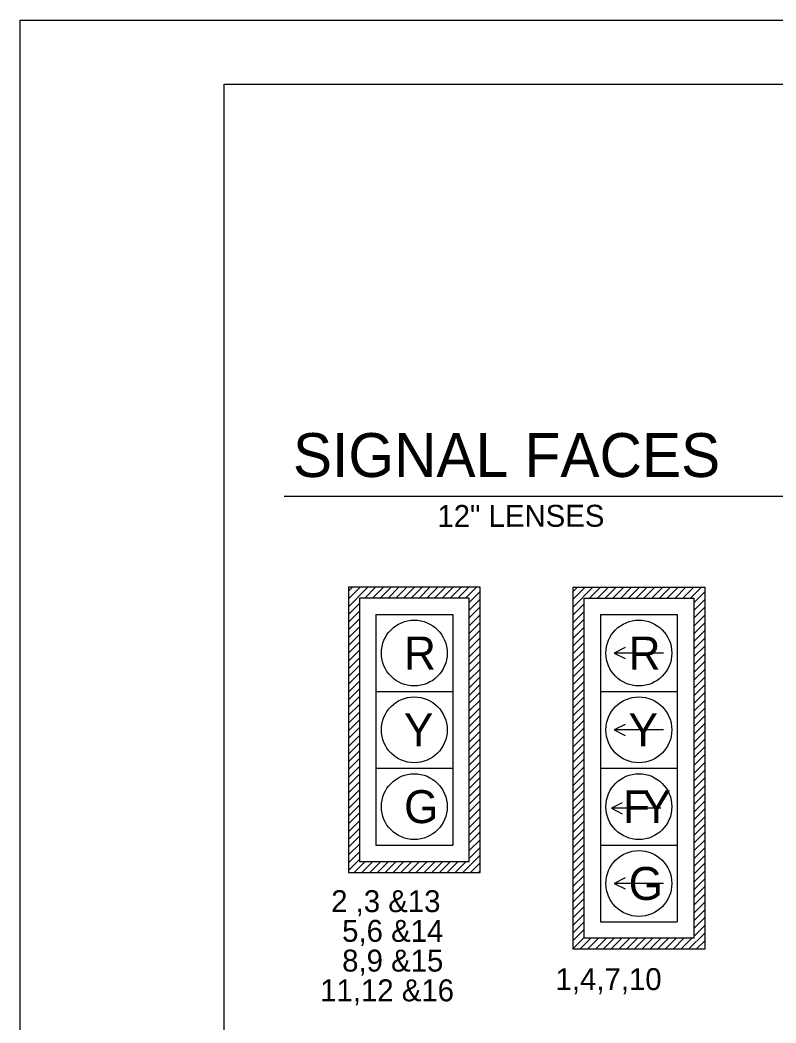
# Model space of a CAD drawing. Extents: x 641001 to 642001, y 326365 to 327005.
# Drawn here: x 641001.3 to 641139.1, y 326822.2 to 327005 of the extents above; entities that cross this region are included whole.
import ezdxf

# ---------------------------------------------------------------- set-up
doc = ezdxf.new("R2010")
doc.units = 0
for name, color, linetype in [('R_Border', 7, 'Continuous'), ('R_No Plot', 7, 'Continuous'), ('T_Drafting', 7, 'Continuous'), ('T_Notes', 7, 'Continuous')]:
    doc.layers.add(name, color=color, linetype=linetype)

msp = doc.modelspace()

# ---------------------------------------------------------------- linework, layer by layer
at = {"layer": 'R_Border'}
for p, q in [((641038.57, 326993.34), (641987.11, 326993.34)), ((641038.57, 326376.96), (641038.57, 326993.34))]:
    msp.add_line(p, q, dxfattribs=at)
at = {"layer": 'R_No Plot'}
msp.add_line((641001.36, 327005.02), (642001.36, 327005.02), dxfattribs=at)
msp.add_lwpolyline([(641001.34, 327005.02), (642001.36, 327005.02), (642001.36, 326365.01), (641001.34, 326365.01)], close=True, dxfattribs=at)
at = {"layer": 'T_Drafting'}
for p, q in [((641085.2, 326901.64), (641061.2, 326901.64)), ((641061.2, 326901.64), (641061.2, 326849.64)), ((641061.2, 326898.09), (641064.75, 326901.64)), ((641061.2, 326899.5), (641063.34, 326901.64)), ((641061.2, 326900.92), (641061.92, 326901.64)), ((641064.16, 326899.64), (641066.16, 326901.64)), ((641065.58, 326899.64), (641067.58, 326901.64)), ((641066.99, 326899.64), (641068.99, 326901.64)), ((641068.41, 326899.64), (641070.41, 326901.64)), ((641069.82, 326899.64), (641071.82, 326901.64)), ((641071.24, 326899.64), (641073.24, 326901.64)), ((641072.65, 326899.64), (641074.65, 326901.64)), ((641074.06, 326899.64), (641076.06, 326901.64)), ((641075.48, 326899.64), (641077.48, 326901.64)), ((641076.89, 326899.64), (641078.89, 326901.64)), ((641078.31, 326899.64), (641080.31, 326901.64)), ((641079.72, 326899.64), (641081.72, 326901.64)), ((641081.14, 326899.64), (641083.14, 326901.64)), ((641082.55, 326899.64), (641084.55, 326901.64)), ((641083.2, 326898.88), (641085.2, 326900.88)), ((641085.2, 326849.64), (641085.2, 326901.64)), ((641102.14, 326835.64), (641102.14, 326901.64)), ((641102.14, 326901.64), (641126.14, 326901.64)), ((641102.14, 326898.03), (641105.75, 326901.64)), ((641102.14, 326899.44), (641104.33, 326901.64)), ((641102.14, 326900.86), (641102.92, 326901.64)), ((641105.16, 326899.64), (641107.16, 326901.64)), ((641106.58, 326899.64), (641108.58, 326901.64)), ((641107.99, 326899.64), (641109.99, 326901.64)), ((641109.41, 326899.64), (641111.41, 326901.64)), ((641110.82, 326899.64), (641112.82, 326901.64)), ((641112.23, 326899.64), (641114.23, 326901.64)), ((641113.65, 326899.64), (641115.65, 326901.64)), ((641115.06, 326899.64), (641117.06, 326901.64)), ((641116.48, 326899.64), (641118.48, 326901.64)), ((641117.89, 326899.64), (641119.89, 326901.64)), ((641119.3, 326899.64), (641121.3, 326901.64)), ((641120.72, 326899.64), (641122.72, 326901.64)), ((641122.13, 326899.64), (641124.13, 326901.64)), ((641123.55, 326899.64), (641125.55, 326901.64)), ((641124.14, 326898.82), (641126.14, 326900.82)), ((641126.14, 326901.64), (641126.14, 326835.64)), ((641061.2, 326896.67), (641063.2, 326898.67)), ((641083.2, 326897.46), (641085.2, 326899.46)), ((641102.14, 326896.61), (641104.14, 326898.61)), ((641124.14, 326897.4), (641126.14, 326899.4)), ((641061.2, 326895.26), (641063.2, 326897.26)), ((641066.2, 326896.64), (641080.2, 326896.64)), ((641066.2, 326896.64), (641066.2, 326882.64)), ((641080.2, 326896.64), (641080.2, 326882.64)), ((641083.2, 326896.05), (641085.2, 326898.05)), ((641083.2, 326894.63), (641085.2, 326896.63)), ((641102.14, 326895.2), (641104.14, 326897.2)), ((641107.14, 326896.64), (641121.14, 326896.64)), ((641107.14, 326896.64), (641107.14, 326882.64)), ((641121.14, 326896.64), (641121.14, 326882.64)), ((641124.14, 326895.99), (641126.14, 326897.99)), ((641124.14, 326894.57), (641126.14, 326896.57)), ((641061.2, 326893.85), (641063.2, 326895.85)), ((641083.2, 326893.22), (641085.2, 326895.22)), ((641102.14, 326893.79), (641104.14, 326895.79)), ((641124.14, 326893.16), (641126.14, 326895.16)), ((641061.2, 326892.43), (641063.2, 326894.43)), ((641061.2, 326891.02), (641063.2, 326893.02)), ((641083.2, 326891.8), (641085.2, 326893.8)), ((641102.14, 326892.37), (641104.14, 326894.37)), ((641102.14, 326890.96), (641104.14, 326892.96)), ((641124.14, 326891.74), (641126.14, 326893.74)), ((641061.2, 326889.6), (641063.2, 326891.6)), ((641083.2, 326890.39), (641085.2, 326892.39)), ((641083.2, 326888.98), (641085.2, 326890.98)), ((641102.14, 326889.54), (641104.14, 326891.54)), ((641124.14, 326890.33), (641126.14, 326892.33)), ((641124.14, 326888.92), (641126.14, 326890.92)), ((641061.2, 326888.19), (641063.2, 326890.19)), ((641083.2, 326887.56), (641085.2, 326889.56)), ((641102.14, 326888.13), (641104.14, 326890.13)), ((641118.64, 326889.64), (641109.64, 326889.64)), ((641124.14, 326887.5), (641126.14, 326889.5)), ((641061.2, 326886.78), (641063.2, 326888.78)), ((641061.2, 326885.36), (641063.2, 326887.36)), ((641083.2, 326886.15), (641085.2, 326888.15)), ((641102.14, 326886.71), (641104.14, 326888.71)), ((641102.14, 326885.3), (641104.14, 326887.3)), ((641124.14, 326886.09), (641126.14, 326888.09)), ((641061.2, 326883.95), (641063.2, 326885.95)), ((641083.2, 326884.73), (641085.2, 326886.73)), ((641102.14, 326883.89), (641104.14, 326885.89)), ((641124.14, 326884.67), (641126.14, 326886.67)), ((641061.2, 326882.53), (641063.2, 326884.53)), ((641083.2, 326883.32), (641085.2, 326885.32)), ((641083.2, 326881.91), (641085.2, 326883.91)), ((641102.14, 326882.47), (641104.14, 326884.47)), ((641124.14, 326883.26), (641126.14, 326885.26)), ((641124.14, 326881.84), (641126.14, 326883.84)), ((641061.2, 326881.12), (641063.2, 326883.12)), ((641066.2, 326882.64), (641080.2, 326882.64)), ((641066.2, 326882.64), (641066.2, 326868.64)), ((641080.2, 326882.64), (641080.2, 326868.64)), ((641083.2, 326880.49), (641085.2, 326882.49)), ((641102.14, 326881.06), (641104.14, 326883.06)), ((641107.14, 326882.64), (641121.14, 326882.64)), ((641107.14, 326882.64), (641107.14, 326868.64)), ((641121.14, 326882.64), (641121.14, 326868.64)), ((641124.14, 326880.43), (641126.14, 326882.43)), ((641061.2, 326879.7), (641063.2, 326881.7)), ((641061.2, 326878.29), (641063.2, 326880.29)), ((641083.2, 326879.08), (641085.2, 326881.08)), ((641102.14, 326879.64), (641104.14, 326881.64)), ((641102.14, 326878.23), (641104.14, 326880.23)), ((641124.14, 326879.02), (641126.14, 326881.02)), ((641061.2, 326876.88), (641063.2, 326878.88)), ((641083.2, 326877.66), (641085.2, 326879.66)), ((641083.2, 326876.25), (641085.2, 326878.25)), ((641102.14, 326876.82), (641104.14, 326878.82)), ((641124.14, 326877.6), (641126.14, 326879.6)), ((641124.14, 326876.19), (641126.14, 326878.19)), ((641061.2, 326875.46), (641063.2, 326877.46)), ((641083.2, 326874.83), (641085.2, 326876.83)), ((641102.14, 326875.4), (641104.14, 326877.4)), ((641124.14, 326874.77), (641126.14, 326876.77)), ((641061.2, 326874.05), (641063.2, 326876.05)), ((641061.2, 326872.63), (641063.2, 326874.63)), ((641083.2, 326873.42), (641085.2, 326875.42)), ((641102.14, 326873.99), (641104.14, 326875.99)), ((641102.14, 326872.57), (641104.14, 326874.57)), ((641118.64, 326875.64), (641109.64, 326875.64)), ((641124.14, 326873.36), (641126.14, 326875.36)), ((641061.2, 326871.22), (641063.2, 326873.22)), ((641083.2, 326872.01), (641085.2, 326874.01)), ((641083.2, 326870.59), (641085.2, 326872.59)), ((641102.14, 326871.16), (641104.14, 326873.16)), ((641124.14, 326871.95), (641126.14, 326873.95)), ((641061.2, 326869.8), (641063.2, 326871.8)), ((641083.2, 326869.18), (641085.2, 326871.18)), ((641102.14, 326869.74), (641104.14, 326871.74)), ((641124.14, 326870.53), (641126.14, 326872.53)), ((641124.14, 326869.12), (641126.14, 326871.12)), ((641061.2, 326868.39), (641063.2, 326870.39)), ((641061.2, 326866.98), (641063.2, 326868.98)), ((641083.2, 326867.76), (641085.2, 326869.76)), ((641102.14, 326868.33), (641104.14, 326870.33)), ((641102.14, 326866.92), (641104.14, 326868.92)), ((641124.14, 326867.7), (641126.14, 326869.7)), ((641061.2, 326865.56), (641063.2, 326867.56)), ((641066.2, 326868.64), (641080.2, 326868.64)), ((641066.2, 326868.64), (641066.2, 326854.64)), ((641080.2, 326868.64), (641080.2, 326854.64)), ((641083.2, 326866.35), (641085.2, 326868.35)), ((641102.14, 326865.5), (641104.14, 326867.5)), ((641107.14, 326868.64), (641121.14, 326868.64)), ((641107.14, 326868.64), (641107.14, 326854.64)), ((641121.14, 326868.64), (641121.14, 326854.64)), ((641124.14, 326866.29), (641126.14, 326868.29)), ((641061.2, 326864.15), (641063.2, 326866.15)), ((641083.2, 326864.93), (641085.2, 326866.93)), ((641083.2, 326863.52), (641085.2, 326865.52)), ((641102.14, 326864.09), (641104.14, 326866.09)), ((641124.14, 326864.87), (641126.14, 326866.87)), ((641124.14, 326863.46), (641126.14, 326865.46)), ((641061.2, 326862.73), (641063.2, 326864.73)), ((641083.2, 326862.11), (641085.2, 326864.11)), ((641102.14, 326862.67), (641104.14, 326864.67)), ((641124.14, 326862.05), (641126.14, 326864.05)), ((641061.2, 326861.32), (641063.2, 326863.32)), ((641061.2, 326859.91), (641063.2, 326861.91)), ((641083.2, 326860.69), (641085.2, 326862.69)), ((641102.14, 326861.26), (641104.14, 326863.26)), ((641102.14, 326859.84), (641104.14, 326861.84)), ((641124.14, 326860.63), (641126.14, 326862.63)), ((641061.2, 326858.49), (641063.2, 326860.49)), ((641083.2, 326859.28), (641085.2, 326861.28)), ((641083.2, 326857.86), (641085.2, 326859.86)), ((641102.14, 326858.43), (641104.14, 326860.43)), ((641118.12, 326861.36), (641109.12, 326861.36)), ((641124.14, 326859.22), (641126.14, 326861.22)), ((641124.14, 326857.8), (641126.14, 326859.8)), ((641061.2, 326857.08), (641063.2, 326859.08)), ((641083.2, 326856.45), (641085.2, 326858.45)), ((641102.14, 326857.02), (641104.14, 326859.02)), ((641124.14, 326856.39), (641126.14, 326858.39)), ((641061.2, 326855.66), (641063.2, 326857.66)), ((641061.2, 326854.25), (641063.2, 326856.25)), ((641083.2, 326855.03), (641085.2, 326857.03)), ((641102.14, 326855.6), (641104.14, 326857.6)), ((641102.14, 326854.19), (641104.14, 326856.19)), ((641124.14, 326854.97), (641126.14, 326856.97)), ((641061.2, 326852.83), (641063.2, 326854.83)), ((641066.2, 326854.64), (641080.2, 326854.64)), ((641083.2, 326853.62), (641085.2, 326855.62)), ((641102.14, 326852.77), (641104.14, 326854.77)), ((641107.14, 326854.64), (641121.14, 326854.64)), ((641107.14, 326854.64), (641107.14, 326840.64)), ((641121.14, 326854.64), (641121.14, 326840.64)), ((641124.14, 326853.56), (641126.14, 326855.56)), ((641061.2, 326851.42), (641063.2, 326853.42)), ((641082.05, 326849.64), (641085.2, 326852.79)), ((641083.2, 326852.21), (641085.2, 326854.21)), ((641102.14, 326851.36), (641104.14, 326853.36)), ((641124.14, 326852.15), (641126.14, 326854.15)), ((641124.14, 326850.73), (641126.14, 326852.73)), ((641061.2, 326850.01), (641063.2, 326852.01)), ((641062.25, 326849.64), (641064.25, 326851.64)), ((641063.66, 326849.64), (641065.66, 326851.64)), ((641065.08, 326849.64), (641067.08, 326851.64)), ((641066.49, 326849.64), (641068.49, 326851.64)), ((641067.9, 326849.64), (641069.9, 326851.64)), ((641069.32, 326849.64), (641071.32, 326851.64)), ((641070.73, 326849.64), (641072.73, 326851.64)), ((641072.15, 326849.64), (641074.15, 326851.64)), ((641073.56, 326849.64), (641075.56, 326851.64)), ((641074.98, 326849.64), (641076.98, 326851.64)), ((641076.39, 326849.64), (641078.39, 326851.64)), ((641077.8, 326849.64), (641079.8, 326851.64)), ((641079.22, 326849.64), (641081.22, 326851.64)), ((641080.63, 326849.64), (641082.63, 326851.64)), ((641083.46, 326849.64), (641085.2, 326851.38)), ((641102.14, 326849.95), (641104.14, 326851.95)), ((641124.14, 326849.32), (641126.14, 326851.32)), ((641061.2, 326849.64), (641085.2, 326849.64)), ((641084.88, 326849.64), (641085.2, 326849.96)), ((641102.14, 326848.53), (641104.14, 326850.53)), ((641102.14, 326847.12), (641104.14, 326849.12)), ((641124.14, 326847.9), (641126.14, 326849.9)), ((641102.14, 326845.7), (641104.14, 326847.7)), ((641118.64, 326847.64), (641109.64, 326847.64)), ((641124.14, 326846.49), (641126.14, 326848.49)), ((641124.14, 326845.08), (641126.14, 326847.08)), ((641102.14, 326844.29), (641104.14, 326846.29)), ((641124.14, 326843.66), (641126.14, 326845.66)), ((641102.14, 326842.87), (641104.14, 326844.87)), ((641102.14, 326841.46), (641104.14, 326843.46)), ((641124.14, 326842.25), (641126.14, 326844.25)), ((641102.14, 326840.05), (641104.14, 326842.05)), ((641124.14, 326840.83), (641126.14, 326842.83)), ((641102.14, 326838.63), (641104.14, 326840.63)), ((641107.14, 326840.64), (641121.14, 326840.64)), ((641124.14, 326839.42), (641126.14, 326841.42)), ((641124.14, 326838), (641126.14, 326840)), ((641102.14, 326837.22), (641104.14, 326839.22)), ((641123.19, 326835.64), (641126.14, 326838.59)), ((641102.14, 326835.8), (641104.14, 326837.8)), ((641103.39, 326835.64), (641105.39, 326837.64)), ((641104.8, 326835.64), (641106.8, 326837.64)), ((641106.22, 326835.64), (641108.22, 326837.64)), ((641107.63, 326835.64), (641109.63, 326837.64)), ((641109.04, 326835.64), (641111.04, 326837.64)), ((641110.46, 326835.64), (641112.46, 326837.64)), ((641111.87, 326835.64), (641113.87, 326837.64)), ((641113.29, 326835.64), (641115.29, 326837.64)), ((641114.7, 326835.64), (641116.7, 326837.64)), ((641116.12, 326835.64), (641118.12, 326837.64)), ((641117.53, 326835.64), (641119.53, 326837.64)), ((641118.94, 326835.64), (641120.94, 326837.64)), ((641120.36, 326835.64), (641122.36, 326837.64)), ((641121.77, 326835.64), (641123.77, 326837.64)), ((641124.6, 326835.64), (641126.14, 326837.18)), ((641126.14, 326835.64), (641102.14, 326835.64)), ((641126.02, 326835.64), (641126.14, 326835.76))]:
    msp.add_line(p, q, dxfattribs=at)
for points in [[(641083.2, 326851.64), (641083.2, 326899.64), (641063.2, 326899.64), (641063.2, 326851.64)], [(641104.14, 326837.64), (641104.14, 326899.64), (641124.14, 326899.64), (641124.14, 326837.64)]]:
    msp.add_lwpolyline(points, close=True, dxfattribs=at)
for points in [[(641111.64, 326890.64), (641109.64, 326889.64), (641111.64, 326888.64)], [(641111.64, 326876.64), (641109.64, 326875.64), (641111.64, 326874.64)], [(641111.12, 326862.36), (641109.12, 326861.36), (641111.12, 326860.36)], [(641111.64, 326848.64), (641109.64, 326847.64), (641111.64, 326846.64)]]:
    msp.add_lwpolyline(points, dxfattribs=at)
for centre in [(641073.2, 326889.64), (641114.14, 326889.64), (641073.2, 326875.64), (641114.14, 326875.64), (641073.2, 326861.64), (641114.14, 326861.64), (641114.14, 326847.64)]:
    msp.add_circle(centre, 6, dxfattribs=at)
at = {"layer": 'T_Notes'}
msp.add_line((641049.48, 326918.26), (641147.66, 326918.26), dxfattribs=at)

# ---------------------------------------------------------------- texts
at = {"layer": 'T_Drafting'}
msp.add_text('12" LENSES', height=4, rotation=0.072, dxfattribs=at).set_placement((641077.41, 326912.63))
for s, p in [('R', (641071.34, 326886.64)), ('R', (641112.28, 326886.64)), ('Y', (641071.31, 326872.64)), ('Y', (641112.25, 326872.64)), ('G', (641071.34, 326858.64)), ('F', (641111.24, 326858.64)), ('Y', (641114.66, 326858.64)), ('G', (641112.28, 326844.64))]:
    msp.add_text(s, height=6, dxfattribs=at).set_placement(p)
at = {"layer": 'T_Notes'}
for s, height, p in [('SIGNAL FACES', 8, (641051.08, 326921.73)), ('2 ,3 &13', 4, (641058.05, 326842.41)), ('5,6 &14', 4, (641060.05, 326837)), ('8,9 &15', 4, (641060.05, 326831.58)), ('1,4,7,10', 4, (641098.95, 326828.2)), ('11,12 &16', 4, (641056.05, 326826.16))]:
    msp.add_text(s, height=height, dxfattribs=at).set_placement(p)

doc.saveas('drawing.dxf')
